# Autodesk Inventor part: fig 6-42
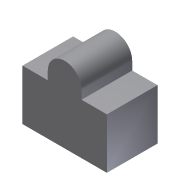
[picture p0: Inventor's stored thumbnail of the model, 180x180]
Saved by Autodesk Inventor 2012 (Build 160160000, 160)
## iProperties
Created: 2005-12
Part Number: fig 6-42
Document SubType Name: Modeling
Designer: CADCIM
Density: 1 g/cm^3
Material: Default
Author: CADCIM
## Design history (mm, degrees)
sketch "Sketch1"
  geometry: L1 (10, 15)-(25, 15); L2 (25, 15)-(25, -15); L3 (25, -15)-(-25, -15); L4 (-25, -15)-(-25, 15); L5 (-25, 15)-(-10, 15); L6 (10, 15)-(10, 30); L7 (10, 30)-(-10, 30); L8 (-10, 30)-(-10, 15)
  constraints: 16 end point, 3 parallel, 3 perpendicular, 2 equal length, 1 collinear, 1 horizontal
  dimensions: "d0" = 50 distance of L2.end L3.end; "d2" = 30 distance of L1.end L2.end; "d3" = 15 distance of L1.start L1.end; "d11" = 15 distance of L7.end L5.end
extrude "Extrusion1" new body sketch "Sketch1" stored distance "d7" = 30; taper "d8" = 0 deg
fillet "Fillet5"
body "Solid1"
